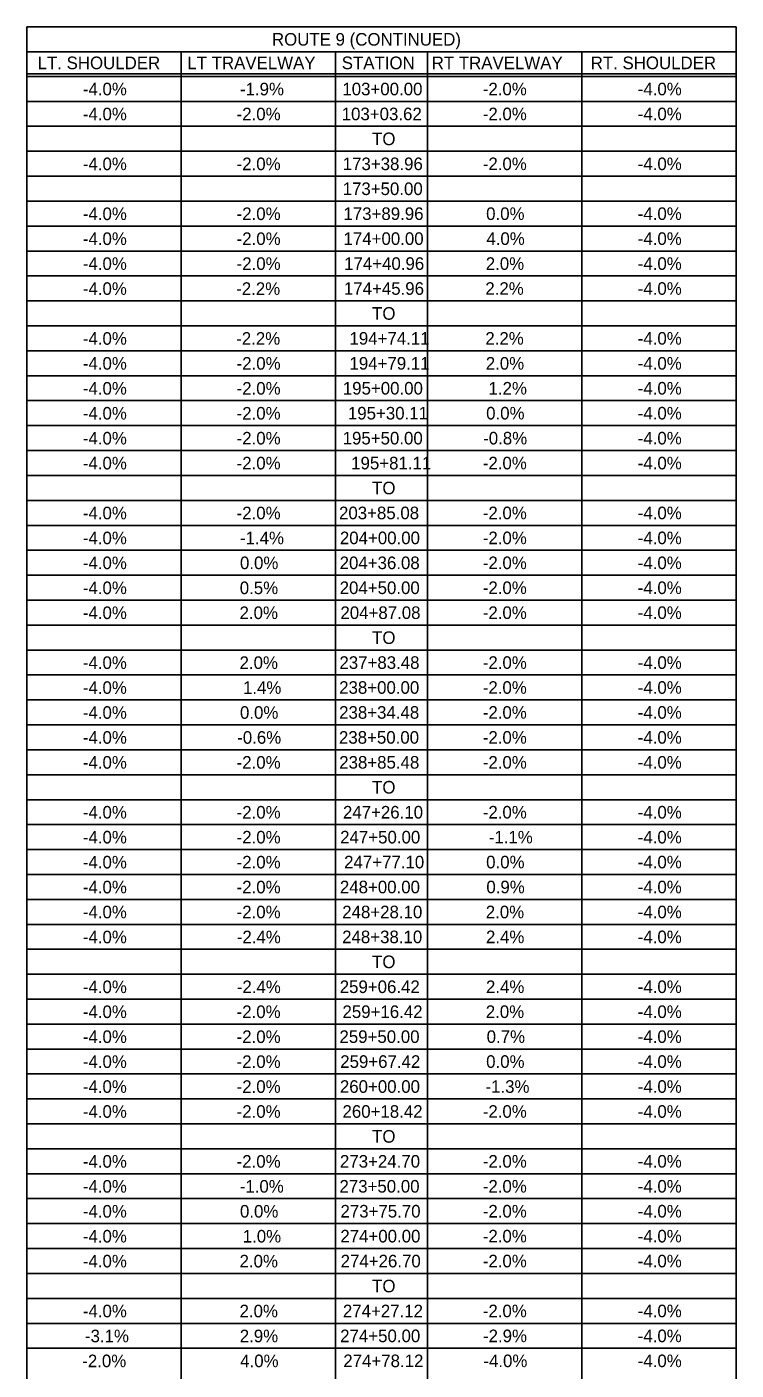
# Model space of a CAD drawing. Extents: x -15318841 to 1762012, y 465773 to 3693661.
# Drawn here: x -15310797.3 to -15310628.3, y 3691122.3 to 3691442.4 of the extents above; entities that cross this region are included whole.
import ezdxf

# ---------------------------------------------------------------- set-up
doc = ezdxf.new("R2010")
doc.units = 0
doc.layers.add('BORDER', color=7, linetype='Continuous')
doc.layers.add('DIMENSIONS', color=7, linetype='Continuous')

msp = doc.modelspace()

# ---------------------------------------------------------------- linework, layer by layer
at = {"layer": 'BORDER'}
for p, q in [((-15310760.51, 3691436.42), (-15310760.51, 3691032.38)), ((-15310723.75, 3691436.42), (-15310723.75, 3691032.38)), ((-15310701.87, 3691436.42), (-15310701.87, 3691032.38)), ((-15310665.1, 3691436.42), (-15310665.1, 3691032.38)), ((-15310797.28, 3691431.14), (-15310628.33, 3691431.14)), ((-15310797.28, 3691430.54), (-15310628.33, 3691430.54)), ((-15310797.28, 3691424.6), (-15310628.33, 3691424.6)), ((-15310797.28, 3691424.6), (-15310628.33, 3691424.6)), ((-15310797.28, 3691424.6), (-15310628.33, 3691424.6)), ((-15310797.28, 3691418.66), (-15310628.33, 3691418.66)), ((-15310797.28, 3691412.71), (-15310628.33, 3691412.71)), ((-15310797.28, 3691406.77), (-15310628.33, 3691406.77)), ((-15310797.28, 3691400.83), (-15310628.33, 3691400.83)), ((-15310797.28, 3691394.88), (-15310628.33, 3691394.88)), ((-15310797.28, 3691388.94), (-15310628.33, 3691388.94)), ((-15310797.28, 3691383), (-15310628.33, 3691383)), ((-15310797.28, 3691377.06), (-15310628.33, 3691377.06)), ((-15310797.28, 3691371.11), (-15310628.33, 3691371.11)), ((-15310797.28, 3691365.17), (-15310628.33, 3691365.17)), ((-15310797.28, 3691359.23), (-15310628.33, 3691359.23)), ((-15310797.28, 3691353.29), (-15310628.33, 3691353.29)), ((-15310797.28, 3691347.34), (-15310628.33, 3691347.34)), ((-15310797.28, 3691341.4), (-15310628.33, 3691341.4)), ((-15310797.28, 3691335.46), (-15310628.33, 3691335.46)), ((-15310797.28, 3691329.51), (-15310628.33, 3691329.51)), ((-15310797.28, 3691323.57), (-15310628.33, 3691323.57)), ((-15310797.28, 3691317.63), (-15310628.33, 3691317.63)), ((-15310797.28, 3691311.69), (-15310628.33, 3691311.69)), ((-15310797.28, 3691305.74), (-15310628.33, 3691305.74)), ((-15310797.28, 3691299.8), (-15310628.33, 3691299.8)), ((-15310797.28, 3691293.86), (-15310628.33, 3691293.86)), ((-15310797.28, 3691287.92), (-15310628.33, 3691287.92)), ((-15310797.28, 3691281.97), (-15310628.33, 3691281.97)), ((-15310797.28, 3691276.03), (-15310628.33, 3691276.03)), ((-15310797.28, 3691270.09), (-15310628.33, 3691270.09)), ((-15310797.28, 3691264.14), (-15310628.33, 3691264.14)), ((-15310797.28, 3691258.2), (-15310628.33, 3691258.2)), ((-15310797.28, 3691252.26), (-15310628.33, 3691252.26)), ((-15310797.28, 3691246.32), (-15310628.33, 3691246.32)), ((-15310797.28, 3691240.37), (-15310628.33, 3691240.37)), ((-15310797.28, 3691234.43), (-15310628.33, 3691234.43)), ((-15310797.28, 3691228.49), (-15310628.33, 3691228.49)), ((-15310797.28, 3691222.55), (-15310628.33, 3691222.55)), ((-15310797.28, 3691216.6), (-15310628.33, 3691216.6)), ((-15310797.28, 3691210.66), (-15310628.33, 3691210.66)), ((-15310797.28, 3691204.72), (-15310628.33, 3691204.72)), ((-15310797.28, 3691198.78), (-15310628.33, 3691198.78)), ((-15310797.28, 3691192.83), (-15310628.33, 3691192.83)), ((-15310797.28, 3691186.89), (-15310628.33, 3691186.89)), ((-15310797.28, 3691180.95), (-15310628.33, 3691180.95)), ((-15310797.28, 3691175), (-15310628.33, 3691175)), ((-15310797.28, 3691169.06), (-15310628.33, 3691169.06)), ((-15310797.28, 3691163.12), (-15310628.33, 3691163.12)), ((-15310797.28, 3691157.18), (-15310628.33, 3691157.18)), ((-15310797.28, 3691151.23), (-15310628.33, 3691151.23)), ((-15310797.28, 3691145.29), (-15310628.33, 3691145.29)), ((-15310797.28, 3691139.35), (-15310628.33, 3691139.35)), ((-15310797.28, 3691133.41), (-15310628.33, 3691133.41)), ((-15310797.28, 3691127.46), (-15310628.33, 3691127.46))]:
    msp.add_line(p, q, dxfattribs=at)
msp.add_lwpolyline([(-15310797.28, 3691436.42), (-15310797.28, 3691442.36), (-15310628.33, 3691442.36), (-15310628.33, 3691436.42)], dxfattribs=at)
msp.add_lwpolyline([(-15310797.28, 3691436.42), (-15310628.33, 3691436.42), (-15310628.33, 3691032.38), (-15310797.28, 3691032.38)], close=True, dxfattribs=at)

# ---------------------------------------------------------------- texts
at = {"layer": 'DIMENSIONS'}
for s, p in [('ROUTE 9 (CONTINUED)', (-15310738.9, 3691437.89)), ('LT. SHOULDER', (-15310794.73, 3691432.28)), ('LT TRAVELWAY', (-15310759.06, 3691432.28)), ('STATION', (-15310722.28, 3691432.28)), ('RT TRAVELWAY', (-15310700.85, 3691432.28)), ('RT. SHOULDER', (-15310662.98, 3691432.28)), ('-4.0%', (-15310783.95, 3691426.04)), ('-1.9%', (-15310746.52, 3691426.04)), ('103+00.00', (-15310722.13, 3691426.05)), ('-2.0%', (-15310688.68, 3691426.05)), ('-4.0%', (-15310651.77, 3691426.05)), ('-4.0%', (-15310783.95, 3691420.09)), ('-2.0%', (-15310747.32, 3691420.09)), ('103+03.62', (-15310722.29, 3691420.11)), ('-2.0%', (-15310688.68, 3691420.11)), ('-4.0%', (-15310651.77, 3691420.11)), ('TO', (-15310715.05, 3691414.17)), ('-4.0%', (-15310783.95, 3691408.21)), ('-2.0%', (-15310747.32, 3691408.21)), ('173+38.96', (-15310722.04, 3691408.22)), ('-2.0%', (-15310688.68, 3691408.22)), ('-4.0%', (-15310651.77, 3691408.22)), ('173+50.00', (-15310722.06, 3691402.28)), ('-4.0%', (-15310783.95, 3691396.32)), ('-2.0%', (-15310747.32, 3691396.32)), ('173+89.96', (-15310721.87, 3691396.34)), ('0.0%', (-15310687.88, 3691396.34)), ('-4.0%', (-15310651.77, 3691396.34)), ('-4.0%', (-15310783.95, 3691390.38)), ('-2.0%', (-15310747.32, 3691390.38)), ('174+00.00', (-15310721.85, 3691390.4)), ('4.0%', (-15310687.83, 3691390.4)), ('-4.0%', (-15310651.77, 3691390.4)), ('-4.0%', (-15310783.95, 3691384.44)), ('-2.0%', (-15310747.32, 3691384.44)), ('174+40.96', (-15310721.71, 3691384.45)), ('2.0%', (-15310687.97, 3691384.45)), ('-4.0%', (-15310651.77, 3691384.45)), ('-4.0%', (-15310783.95, 3691378.49)), ('-2.2%', (-15310747.42, 3691378.49)), ('174+45.96', (-15310721.76, 3691378.51)), ('2.2%', (-15310688.07, 3691378.51)), ('-4.0%', (-15310651.77, 3691378.51)), ('TO', (-15310715.05, 3691372.57)), ('-4.0%', (-15310783.95, 3691366.61)), ('-2.2%', (-15310747.42, 3691366.61)), ('194+74.11', (-15310720.43, 3691366.63)), ('2.2%', (-15310688.07, 3691366.63)), ('-4.0%', (-15310651.77, 3691366.63)), ('-4.0%', (-15310783.95, 3691360.67)), ('-2.0%', (-15310747.32, 3691360.67)), ('194+79.11', (-15310720.43, 3691360.68)), ('2.0%', (-15310687.97, 3691360.68)), ('-4.0%', (-15310651.77, 3691360.68)), ('-4.0%', (-15310783.95, 3691354.72)), ('-2.0%', (-15310747.32, 3691354.72)), ('195+00.00', (-15310722.02, 3691354.74)), ('1.2%', (-15310687.31, 3691354.74)), ('-4.0%', (-15310651.77, 3691354.74)), ('-4.0%', (-15310783.95, 3691348.78)), ('-2.0%', (-15310747.32, 3691348.78)), ('195+30.11', (-15310720.81, 3691348.8)), ('0.0%', (-15310687.88, 3691348.8)), ('-4.0%', (-15310651.77, 3691348.8)), ('-4.0%', (-15310783.95, 3691342.84)), ('-2.0%', (-15310747.32, 3691342.84)), ('195+50.00', (-15310722.06, 3691342.85)), ('-0.8%', (-15310688.59, 3691342.85)), ('-4.0%', (-15310651.77, 3691342.85)), ('-4.0%', (-15310783.95, 3691336.9)), ('-2.0%', (-15310747.32, 3691336.9)), ('195+81.11', (-15310720.03, 3691336.91)), ('-2.0%', (-15310688.68, 3691336.91)), ('-4.0%', (-15310651.77, 3691336.91)), ('TO', (-15310715.05, 3691330.97)), ('-4.0%', (-15310783.95, 3691325.01)), ('-2.0%', (-15310747.32, 3691325.01)), ('203+85.08', (-15310722.93, 3691325.03)), ('-2.0%', (-15310688.68, 3691325.03)), ('-4.0%', (-15310651.77, 3691325.03)), ('-4.0%', (-15310783.95, 3691319.07)), ('-1.4%', (-15310746.52, 3691319.07)), ('204+00.00', (-15310722.72, 3691319.08)), ('-2.0%', (-15310688.68, 3691319.08)), ('-4.0%', (-15310651.77, 3691319.08)), ('-4.0%', (-15310783.95, 3691313.13)), ('0.0%', (-15310746.52, 3691313.13)), ('204+36.08', (-15310722.78, 3691313.14)), ('-2.0%', (-15310688.68, 3691313.14)), ('-4.0%', (-15310651.77, 3691313.14)), ('-4.0%', (-15310783.95, 3691307.18)), ('0.5%', (-15310746.57, 3691307.18)), ('204+50.00', (-15310722.77, 3691307.2)), ('-2.0%', (-15310688.68, 3691307.2)), ('-4.0%', (-15310651.77, 3691307.2)), ('-4.0%', (-15310783.95, 3691301.24)), ('2.0%', (-15310746.62, 3691301.24)), ('204+87.08', (-15310722.59, 3691301.26)), ('-2.0%', (-15310688.68, 3691301.26)), ('-4.0%', (-15310651.77, 3691301.26)), ('TO', (-15310715.05, 3691295.31)), ('-4.0%', (-15310783.95, 3691289.35)), ('2.0%', (-15310746.62, 3691289.35)), ('237+83.48', (-15310722.83, 3691289.37)), ('-2.0%', (-15310688.68, 3691289.37)), ('-4.0%', (-15310651.77, 3691289.37)), ('-4.0%', (-15310783.95, 3691283.41)), ('1.4%', (-15310745.81, 3691283.41)), ('238+00.00', (-15310722.89, 3691283.43)), ('-2.0%', (-15310688.68, 3691283.43)), ('-4.0%', (-15310651.77, 3691283.43)), ('-4.0%', (-15310783.95, 3691277.47)), ('0.0%', (-15310746.52, 3691277.47)), ('238+34.48', (-15310722.9, 3691277.49)), ('-2.0%', (-15310688.68, 3691277.49)), ('-4.0%', (-15310651.77, 3691277.49)), ('-4.0%', (-15310783.95, 3691271.53)), ('-0.6%', (-15310747.18, 3691271.53)), ('238+50.00', (-15310722.94, 3691271.54)), ('-2.0%', (-15310688.68, 3691271.54)), ('-4.0%', (-15310651.77, 3691271.54)), ('-4.0%', (-15310783.95, 3691265.58)), ('-2.0%', (-15310747.32, 3691265.58)), ('238+85.48', (-15310722.88, 3691265.6)), ('-2.0%', (-15310688.68, 3691265.6)), ('-4.0%', (-15310651.77, 3691265.6)), ('TO', (-15310715.05, 3691259.66)), ('-4.0%', (-15310783.95, 3691253.7)), ('-2.0%', (-15310747.32, 3691253.7)), ('247+26.10', (-15310721.99, 3691253.71)), ('-2.0%', (-15310688.68, 3691253.71)), ('-4.0%', (-15310651.77, 3691253.71)), ('-4.0%', (-15310783.95, 3691247.76)), ('-2.0%', (-15310747.32, 3691247.76)), ('247+50.00', (-15310722.65, 3691247.77)), ('-1.1%', (-15310687.26, 3691247.77)), ('-4.0%', (-15310651.77, 3691247.77)), ('-4.0%', (-15310783.95, 3691241.81)), ('-2.0%', (-15310747.32, 3691241.81)), ('247+77.10', (-15310721.71, 3691241.83)), ('0.0%', (-15310687.88, 3691241.83)), ('-4.0%', (-15310651.77, 3691241.83)), ('-4.0%', (-15310783.95, 3691235.87)), ('-2.0%', (-15310747.32, 3691235.87)), ('248+00.00', (-15310722.72, 3691235.89)), ('0.9%', (-15310687.83, 3691235.89)), ('-4.0%', (-15310651.77, 3691235.89)), ('-4.0%', (-15310783.95, 3691229.93)), ('-2.0%', (-15310747.32, 3691229.93)), ('248+28.10', (-15310722.16, 3691229.94)), ('2.0%', (-15310687.97, 3691229.94)), ('-4.0%', (-15310651.77, 3691229.94)), ('-4.0%', (-15310783.95, 3691223.98)), ('-2.4%', (-15310747.28, 3691223.98)), ('248+38.10', (-15310722.18, 3691224)), ('2.4%', (-15310687.92, 3691224)), ('-4.0%', (-15310651.77, 3691224)), ('TO', (-15310715.05, 3691218.06)), ('-4.0%', (-15310783.95, 3691212.1)), ('-2.4%', (-15310747.28, 3691212.1)), ('259+06.42', (-15310722.76, 3691212.12)), ('2.4%', (-15310687.92, 3691212.12)), ('-4.0%', (-15310651.77, 3691212.12)), ('-4.0%', (-15310783.95, 3691206.16)), ('-2.0%', (-15310747.32, 3691206.16)), ('259+16.42', (-15310722.1, 3691206.17)), ('2.0%', (-15310687.97, 3691206.17)), ('-4.0%', (-15310651.77, 3691206.17)), ('-4.0%', (-15310783.95, 3691200.21)), ('-2.0%', (-15310747.32, 3691200.21)), ('259+50.00', (-15310722.82, 3691200.23)), ('0.7%', (-15310687.76, 3691200.23)), ('-4.0%', (-15310651.77, 3691200.23)), ('-4.0%', (-15310783.95, 3691194.27)), ('-2.0%', (-15310747.32, 3691194.27)), ('259+67.42', (-15310722.64, 3691194.29)), ('0.0%', (-15310687.88, 3691194.29)), ('-4.0%', (-15310651.77, 3691194.29)), ('-4.0%', (-15310783.95, 3691188.33)), ('-2.0%', (-15310747.32, 3691188.33)), ('260+00.00', (-15310722.72, 3691188.34)), ('-1.3%', (-15310688.04, 3691188.34)), ('-4.0%', (-15310651.77, 3691188.34)), ('-4.0%', (-15310783.95, 3691182.39)), ('-2.0%', (-15310747.32, 3691182.39)), ('260+18.42', (-15310722.1, 3691182.4)), ('-2.0%', (-15310688.68, 3691182.4)), ('-4.0%', (-15310651.77, 3691182.4)), ('TO', (-15310715.05, 3691176.46)), ('-4.0%', (-15310783.95, 3691170.5)), ('-2.0%', (-15310747.32, 3691170.5)), ('273+24.70', (-15310722.7, 3691170.52)), ('-2.0%', (-15310688.68, 3691170.52)), ('-4.0%', (-15310651.77, 3691170.52)), ('-4.0%', (-15310783.95, 3691164.56)), ('-1.0%', (-15310746.57, 3691164.56)), ('273+50.00', (-15310722.82, 3691164.57)), ('-2.0%', (-15310688.68, 3691164.57)), ('-4.0%', (-15310651.77, 3691164.57)), ('-4.0%', (-15310783.95, 3691158.61)), ('0.0%', (-15310746.52, 3691158.61)), ('273+75.70', (-15310722.58, 3691158.63)), ('-2.0%', (-15310688.68, 3691158.63)), ('-4.0%', (-15310651.77, 3691158.63)), ('-4.0%', (-15310783.95, 3691152.67)), ('1.0%', (-15310745.86, 3691152.67)), ('274+00.00', (-15310722.61, 3691152.69)), ('-2.0%', (-15310688.68, 3691152.69)), ('-4.0%', (-15310651.77, 3691152.69)), ('-4.0%', (-15310783.95, 3691146.73)), ('2.0%', (-15310746.62, 3691146.73)), ('274+26.70', (-15310722.54, 3691146.75)), ('-2.0%', (-15310688.68, 3691146.75)), ('-4.0%', (-15310651.77, 3691146.75)), ('TO', (-15310715.05, 3691140.8)), ('-4.0%', (-15310783.95, 3691134.84)), ('2.0%', (-15310746.62, 3691134.84)), ('274+27.12', (-15310722, 3691134.86)), ('-2.0%', (-15310688.68, 3691134.86)), ('-4.0%', (-15310651.77, 3691134.86)), ('-3.1%', (-15310783.45, 3691128.9)), ('2.9%', (-15310746.57, 3691128.9)), ('274+50.00', (-15310722.65, 3691128.92)), ('-2.9%', (-15310688.63, 3691128.92)), ('-4.0%', (-15310651.77, 3691128.92)), ('-2.0%', (-15310784.09, 3691122.96)), ('4.0%', (-15310746.47, 3691122.96)), ('274+78.12', (-15310721.91, 3691122.97)), ('-4.0%', (-15310688.54, 3691122.97)), ('-4.0%', (-15310651.77, 3691122.97))]:
    msp.add_text(s, height=3, dxfattribs=at).set_placement(p)

doc.saveas('drawing.dxf')
